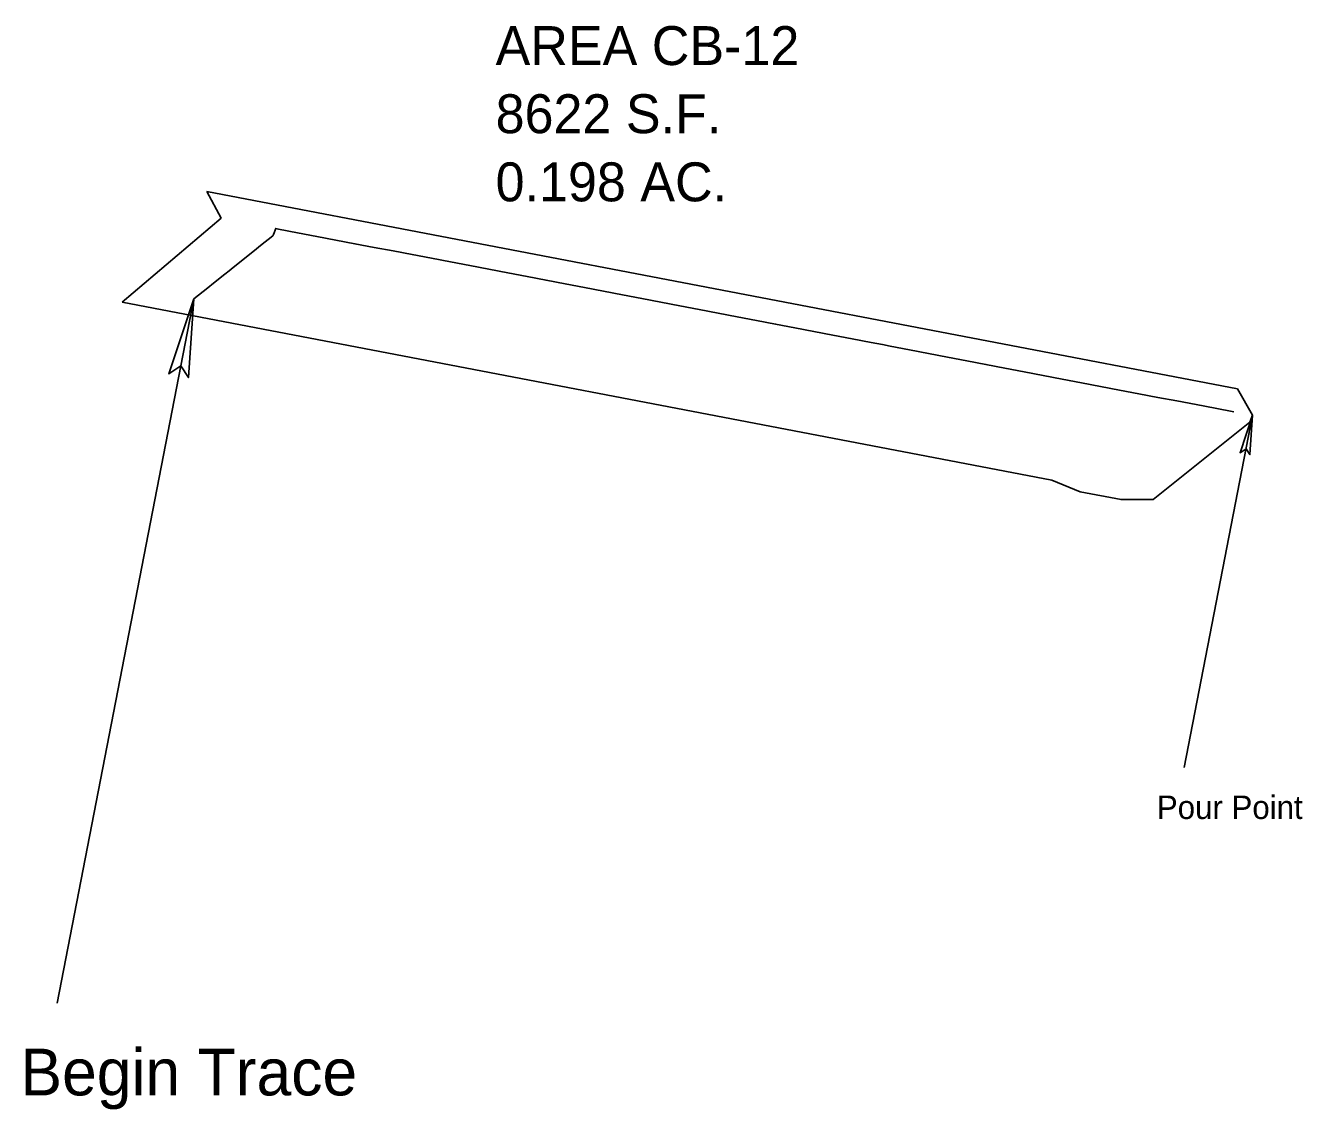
# Model space of a CAD drawing. Extents: x 3451 to 3779, y 2886 to 3165.
import ezdxf

# ---------------------------------------------------------------- set-up
doc = ezdxf.new("R2010")
doc.units = 0
for name, color, linetype in [('Default', 7, 'Continuous'), ('DESIGN - SCRATCH - User 1', 7, 'Continuous'), ('SURVEY - CENTERLINE - Preliminary', 7, 'Continuous'), ('SURVEY - CENTERLINE - Preliminary Text', 7, 'Continuous'), ('SURVEY - DRAINAGE - Area Shapes', 7, 'Continuous')]:
    doc.layers.add(name, color=color, linetype=linetype)

msp = doc.modelspace()

# ---------------------------------------------------------------- linework, layer by layer
at = {"layer": 'DESIGN - SCRATCH - User 1'}
msp.add_line((3766.32, 3064.63), (3748.78, 2974.19), dxfattribs=at)
msp.add_lwpolyline([(3766.32, 3064.63), (3765.63, 3054.53), (3764.65, 3056.04), (3763.13, 3055.02)], close=True, dxfattribs=at)
msp.add_lwpolyline([(3766.32, 3064.63), (3765.63, 3054.53), (3764.65, 3056.04), (3763.13, 3055.02), (3766.32, 3064.63)], dxfattribs=at)
at = {"layer": 'SURVEY - CENTERLINE - Preliminary'}
msp.add_lwpolyline([(3494.34, 3094.5), (3497.94, 3097.39), (3499.37, 3098.53), (3502.29, 3100.86), (3503.41, 3101.76), (3503.95, 3102.19), (3507.45, 3104.99), (3509.96, 3107), (3511.49, 3108.22), (3514.62, 3110.72), (3514.78, 3111.11), (3515.39, 3112.61), (3516.1, 3112.47), (3521.01, 3111.53), (3525.92, 3110.59), (3530.83, 3109.65), (3535.75, 3108.71), (3540.66, 3107.77), (3545.57, 3106.83), (3550.48, 3105.89), (3555.39, 3104.95), (3560.3, 3104.01), (3565.21, 3103.07), (3570.12, 3102.13), (3575.03, 3101.19), (3579.94, 3100.26), (3584.85, 3099.31), (3589.77, 3098.38), (3594.68, 3097.44), (3599.59, 3096.5), (3604.5, 3095.56), (3609.41, 3094.62), (3614.32, 3093.68), (3619.23, 3092.74), (3624.14, 3091.8), (3629.05, 3090.86), (3633.96, 3089.92), (3638.87, 3088.98), (3643.79, 3088.04), (3648.7, 3087.1), (3653.61, 3086.16), (3658.52, 3085.22), (3663.43, 3084.28), (3668.34, 3083.34), (3671.27, 3082.78), (3673.25, 3082.4), (3678.16, 3081.46), (3683.07, 3080.52), (3687.98, 3079.58), (3692.89, 3078.64), (3697.81, 3077.7), (3702.72, 3076.76), (3707.63, 3075.82), (3712.54, 3074.88), (3717.45, 3073.94), (3722.36, 3073), (3727.27, 3072.06), (3732.18, 3071.12), (3737.09, 3070.18), (3742, 3069.24), (3746.91, 3068.3), (3751.83, 3067.36), (3756.74, 3066.42), (3761.53, 3065.52)], dxfattribs=at)
at = {"layer": 'SURVEY - CENTERLINE - Preliminary Text'}
msp.add_line((3494.34, 3094.5), (3459.28, 2913.61), dxfattribs=at)
msp.add_lwpolyline([(3494.34, 3094.5), (3492.97, 3074.3), (3491.01, 3077.32), (3487.96, 3075.27)], close=True, dxfattribs=at)
msp.add_lwpolyline([(3494.34, 3094.5), (3492.97, 3074.3), (3491.01, 3077.32), (3487.96, 3075.27), (3494.34, 3094.5)], dxfattribs=at)
at = {"layer": 'SURVEY - DRAINAGE - Area Shapes'}
msp.add_line((3475.98, 3093.68), (3475.98, 3093.68), dxfattribs=at)
for points in [[(3497.72, 3122.11), (3501.37, 3115.29), (3475.98, 3093.68)], [(3497.72, 3122.11), (3501.37, 3115.29), (3475.98, 3093.68)], [(3475.98, 3093.68), (3714.79, 3047.98), (3722.08, 3044.94), (3732.55, 3042.98), (3740.78, 3043.01), (3765.61, 3062.9), (3766.32, 3064.63), (3762.43, 3071.45), (3497.72, 3122.11)], [(3497.72, 3122.11), (3497.72, 3122.11)]]:
    msp.add_lwpolyline(points, dxfattribs=at)

# ---------------------------------------------------------------- texts
at = {"layer": 'Default'}
for s, p in [('AREA CB-12', (3571.87, 3154.59)), ('8622 S.F.', (3571.87, 3137.09)), ('0.198 AC.', (3571.87, 3119.59))]:
    msp.add_text(s, height=10, dxfattribs=at).set_placement(p)
at = {"layer": 'DESIGN - SCRATCH - User 1'}
msp.add_text('Pour Point', height=6, dxfattribs=at).set_placement((3741.74, 2960.93))
at = {"layer": 'SURVEY - CENTERLINE - Preliminary Text'}
msp.add_text('Begin Trace', height=12, dxfattribs=at).set_placement((3449.8, 2889.93))

doc.saveas('drawing.dxf')
